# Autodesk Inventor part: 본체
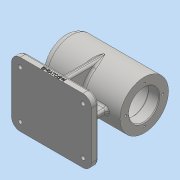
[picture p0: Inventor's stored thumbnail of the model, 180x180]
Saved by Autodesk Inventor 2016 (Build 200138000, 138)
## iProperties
Created: 2020-10
Part Number: 본체
Material: Generic
Document SubType Name: Modeling
Designer: User
Density: 1 g/cm^3
Appearance: Default
Author: User
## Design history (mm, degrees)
sketch "스케치1"
  geometry: L1 (0, 0)-(132.063, 0); L2 (0, 0)-(0, 34); L3 (0, 34)-(112, 34); L4 (112, 34)-(112, 0); L5 (112, 21)-(97, 21); L6 (97, 21)-(97, 24); L7 (97, 24)-(43, 24); L8 (43, 24)-(43, 21); L9 (43, 21)-(31, 21); L10 (31, 21)-(31, 17.5); L11 (31, 17.5)-(13, 17.5); L12 (13, 17.5)-(13, 16); L13 (13, 16)-(9, 16); L14 (9, 16)-(9, 10.5); L15 (9, 10.5)-(6, 10.5); L16 (6, 10.5)-(6, 0)
  constraints: 32 end point, 12 perpendicular, 3 point on line, 2 horizontal, 1 vertical
  dimensions: "d0" = 112 distance of L2.end L3.end; "d1" = 68 diameter of L3 L1; "d2" = 48 diameter of L7 L1; "d3" = 42 diameter of L5 L1; "d5" = 42 diameter of L9 L1; "d8" = 32 diameter of L13 L1; "d9" = 35 diameter of L11 L1; "d10" = 21 diameter of L15 L1; "d11" = 15 distance of L5.start L5.end; "d12" = 54 distance of L6.end L7.end; "d13" = 12 distance of L8.end L9.end; "d14" = 18 distance of L10.end L11.end; "d15" = 4 distance of L12.end L13.end; "d16" = 3 distance of L14.end L15.end
revolve "회전1" sketch "스케치1" stored, may be unused: angle "d17" = 90 deg
fillet "모깎기1" dims "d18" = 3
chamfer "모따기1" distance "d19" = 1; stored, may be unused: second distance "d20" = 2, angle "d21" = 45 deg
fillet "모깎기2" dims "d22" = 0.3
node "작업 평면1"
sketch "스케치2"
  geometry: L1 (0, -45)-(-112, -45); L2 (-112, -45)-(-112, 45); L3 (-112, 45)-(0, 45); L4 (0, 45)-(0, -45); 2 further points
  constraints: 8 end point, 2 parallel, 1 coincident, 1 horizontal, 1 midpoint, 1 perpendicular
  dimensions: "d24" = 112 distance of L1.start L1.end; "d25" = 90 distance of L1.end L2.end
extrude "돌출1" join sketch "스케치2" distance "d26" = 10; taper "d27" = 0 deg
fillet "모깎기3" dims "d28" = 10
fillet "모깎기4" dims "d29" = 12
fillet "모깎기5" dims "d30" = 3
sketch "스케치3"
  geometry: L1 (0, 33)-(0, -33) reference; L2 (112, -33)-(112, 33) reference; L3 (18, 4)-(94, 4); L4 (94, 4)-(94, -4); L5 (94, -4)-(18, -4); L6 (18, -4)-(18, 4); 3 further points
  constraints: 8 end point, 2 midpoint, 2 parallel, 1 horizontal, 1 horizontal alignment, 1 perpendicular
  dimensions: "d31" = 18 distance between parallel lines of L2 L4; "d32" = 18 distance between parallel lines of L1 L6; "d33" = 8 distance of L3.end L4.end
extrude "돌출2" join sketch "스케치3" stored distance "d34" = 10; taper "d35" = 0 deg
sketch "스케치4"
  geometry: L1 (52, 34)-(60, 34); L2 (60, 34)-(60, -34); L3 (60, -34)-(52, -34); L4 (52, -34)-(52, 34); L5 (0, 33)-(0, -33) reference; L6 (100, 45)-(12, 45) reference; L7 (12, -45)-(100, -45) reference; L8 (56, 34)-(56, -34); L9 (112, -33)-(112, 33) reference; 3 further points
  constraints: 10 end point, 4 midpoint, 2 parallel, 1 horizontal, 1 horizontal alignment, 1 perpendicular
  dimensions: "d36" = 8 distance of L1.start L1.end; "d37" = 68 distance of L1.end L2.end; "d38" = 56 distance between parallel lines of L9 L8
extrude "돌출3" join sketch "스케치4" stored distance "d39" = 10; taper "d40" = 0 deg
fillet "모깎기6" dims "d41" = 3
fillet "모깎기7" dims "d42" = 3
fillet "모깎기8" dims "d43" = 3
fillet "모깎기9" dims "d44" = 3
sketch "스케치5"
  geometry: L1 (-12, 6)-(100, 6); L2 (100, 6)-(100, 0); L3 (100, 0)-(-12, 0); L4 (-12, 0)-(-12, 6); L5 (44, 6)-(44, 0); L6 (44, 3)-(100, 3); L7 (100, 0)-(100, 7) reference; L8 (88, 0)-(0, 0) reference; 1 further point
  constraints: 4 end point, 4 midpoint, 2 collinear, 2 other
  dimensions: "d46" = 3 vertical distance of L2.end L6.start; "d67" = 56 horizontal distance of L2.end L6.start
feature "엠보싱1" sketch "스케치5" dims "d0" = 112, "d1" = 68, "d2" = 48, "d3" = 42, "d5" = 42, "d8" = 32, "d9" = 35, "d10" = 21, "d11" = 15, "d12" = 54, "d13" = 12, "d14" = 18, "d15" = 4, "d16" = 3, "d47" = 0.5, "d48" = 0
sketch "스케치6" dims "d49" = 52
  geometry: L1 (0, 0)-(0, 26); 2 further points
  constraints: 2 coincident, 2 end point, 1 vertical, 1 vertical alignment, 2 other
hole "구멍1" sketch "스케치6" at (0, 26) diameter "d50" = 3.242; stored, may be unused: countersink angle "d54" = 90 deg, drill point angle "d56" = 118 deg; dims "d51" = 8, "d52" = 4, "d53" = 2, "d55" = 11
sketch "스케치7"
  geometry: A1 r 12 centre (12, 33) between (12, 45) and (0, 33) reference; A2 r 12 centre (12, -33) between (0, -33) and (12, -45) reference; A3 r 12 centre (100, -33) between (100, -45) and (112, -33) reference; A4 r 12 centre (100, 33) between (112, 33) and (100, 45) reference; 1 further point
hole "구멍2" sketch "스케치7" at (12, -33), (100, -33), (12, 33), (100, 33) diameter "d60" = 5.5; stored, may be unused: countersink angle "d64" = 90 deg, drill point angle "d66" = 118 deg; dims "d61" = 8, "d62" = 9.5, "d63" = 5.4, "d65" = 11
node "솔리드1"
pattern_circular "원형 패턴1" dims angle "d58" = 360 deg
other parameters: "d23" = -74
